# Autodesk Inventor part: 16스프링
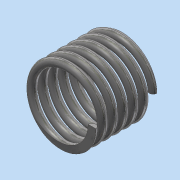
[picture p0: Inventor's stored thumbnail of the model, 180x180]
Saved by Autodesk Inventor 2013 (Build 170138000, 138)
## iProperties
Created: 2019-07
Part Number: 16스프링
Material: 강철, 탄소
Document SubType Name: Modeling
Designer: Administrator
Density: 7.87 g/cm^3
Mass: 7.7127 g
Surface Area: 19.9892 cm^2
Volume: 0.980013 cm^3
Author: Administrator
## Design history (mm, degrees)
sketch "스케치1"
  geometry: L1 (0, 0)-(0, 16); L2 (0, 0)-(8.5, 0); L3 (0, 16)-(8.5, 16); C1 r 1 at (8.5, 0)
  constraints: 6 end point, 2 parallel, 1 centre point, 1 coincident, 1 perpendicular, 1 vertical
  dimensions: "d0" = 16 distance of L1.start L1.end (derived); "d1" = 2 diameter of C1; "d2" = 17 diameter of C1.centre L1
feature "코일1" sketch "스케치1" pitch "d3" = 10; turns "d5" = 6; dims "d4" = 16 (= d0), "d6" = 0, angle "d7" = 90 deg, angle "d8" = 90 deg, "d9" = 0, "d10" = 0
sketch "스케치2"
  geometry: L1 (16, 15)-(0, 15); L2 (0, 15)-(0, -15); L3 (0, -15)-(16, -15); L4 (16, -15)-(16, 15); 2 further points
  constraints: 8 end point, 2 parallel, 1 coincident, 1 horizontal, 1 midpoint, 1 perpendicular
  dimensions: "d11" = 30 distance of L3.end L1.start; "d13" = 16 distance of L2.end L3.end (= d0)
extrude "돌출1" sketch "스케치2" stored distance "d14" = 10; taper "d15" = 0 deg
node "솔리드1"
